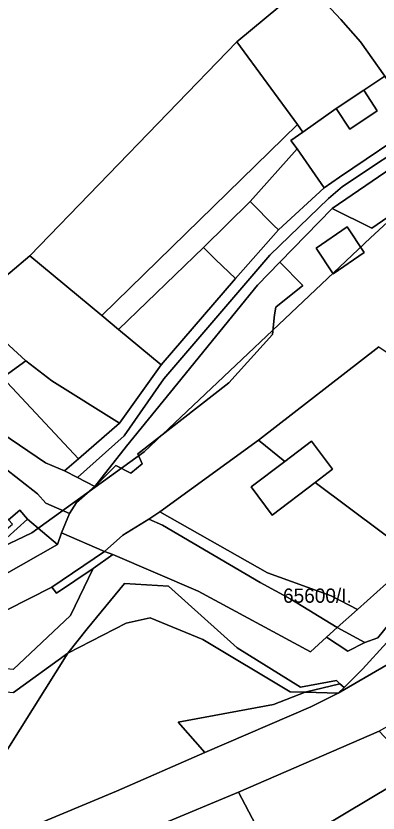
# Model space of a CAD drawing. Extents: x -521261 to -517465, y -1182764 to -1179456.
# Drawn here: x -519071.1 to -518943.8, y -1182060.3 to -1181780.6 of the extents above; entities that cross this region are included whole.
import ezdxf

# ---------------------------------------------------------------- set-up
doc = ezdxf.new("R2010")
doc.units = 0
for name, color, linetype in [('95560013', 7, 'Continuous'), ('95590013', 7, 'Continuous'), ('95610013', 7, 'Continuous'), ('95630013', 7, 'Continuous'), ('95640013', 7, 'Continuous'), ('95660013', 7, 'Continuous')]:
    doc.layers.add(name, color=color, linetype=linetype)

msp = doc.modelspace()

# ---------------------------------------------------------------- linework, layer by layer
at = {"layer": '95560013'}
for points in [[(-519087.04, -1181882.36), (-519066.19, -1181864.73), (-519040.9, -1181885.72), (-519035.04, -1181890.57), (-519020.01, -1181903), (-519034.69, -1181923.51), (-519058.47, -1181908.66), (-519067.58, -1181901.65), (-519076.36, -1181893.5), (-519077.48, -1181892.33), (-519081.67, -1181887.94)], [(-518943.53, -1181896.7), (-518896.41, -1181928.2), (-518898.82, -1181933.95), (-518910.09, -1181942.77), (-518918.49, -1181954.45), (-518930.7, -1181970.59), (-518965.92, -1181944.29), (-518959.85, -1181939.68), (-518967.28, -1181929.78), (-518976.64, -1181936.92), (-518985.81, -1181929.52)], [(-519088.08, -1181916.29), (-519075.82, -1181907.51), (-519049.15, -1181935.98), (-519054.08, -1181940.22), (-519060.67, -1181937.45), (-519082.36, -1181922.81)], [(-518985.81, -1181929.52), (-518976.64, -1181936.92), (-518988.39, -1181945.89), (-518981.04, -1181955.77), (-518965.92, -1181944.29), (-518930.7, -1181970.59), (-518951.03, -1181988.87), (-518960.26, -1181984.07), (-518982.66, -1181976.03), (-519020.51, -1181954.59)], [(-519032.35, -1181993.68), (-519023.89, -1181991.86), (-519005.47, -1181999.42), (-518974.73, -1182017.76), (-518969.43, -1182017.88), (-518980.58, -1182022.19), (-519014.12, -1182028.45), (-519004.74, -1182039.1), (-519035.76, -1182052.6), (-519084.93, -1182073.15), (-519090.2, -1182063.54), (-519052.86, -1182004.21)], [(-519071.99, -1182018.05), (-519052.86, -1182004.21), (-519090.2, -1182063.54), (-519084.93, -1182073.15), (-519102.81, -1182080.62), (-519119.74, -1182088.73), (-519152.16, -1182054.92), (-519144.87, -1182052.15), (-519120.85, -1182036.4), (-519105.37, -1182029.49), (-519087.95, -1182016.65)], [(-518957.82, -1182018.26), (-518967.5, -1182023), (-519004.74, -1182039.1), (-519014.12, -1182028.45), (-518980.58, -1182022.19), (-518969.43, -1182017.88)]]:
    msp.add_lwpolyline(points, close=True, dxfattribs=at)
at = {"layer": '95590013'}
for points in [[(-518986.79, -1181749.85), (-518972.73, -1181724.81), (-518938.29, -1181774.74), (-518915.75, -1181808.56), (-518929.6, -1181818.43), (-518941.47, -1181801.69), (-518950.05, -1181789.67), (-518956.94, -1181781.84), (-518968.7, -1181769.11)], [(-518948.89, -1181806.68), (-518941.47, -1181801.69), (-518929.6, -1181818.43), (-518957.37, -1181837.14), (-518962.74, -1181840.92), (-518972.32, -1181827.26), (-518974.44, -1181824.24), (-518970.25, -1181821.36), (-518958.55, -1181813.11), (-518953.78, -1181820.27), (-518944.13, -1181813.85)]]:
    msp.add_lwpolyline(points, close=True, dxfattribs=at)
at = {"layer": '95610013'}
for points in [[(-519074.15, -1181676.23), (-519053.88, -1181700.18), (-519021, -1181726.81), (-518986.79, -1181749.85), (-518968.7, -1181769.11), (-518993.46, -1181789.66), (-519066.19, -1181864.73), (-519087.04, -1181882.36), (-519108.76, -1181856.75), (-519103.21, -1181844.57), (-519100.47, -1181806.98), (-519098.36, -1181782.29)], [(-518993.46, -1181789.66), (-518972.2, -1181818.68), (-519040.9, -1181885.72), (-519066.19, -1181864.73)], [(-518972.32, -1181827.26), (-518962.74, -1181840.92), (-518978.77, -1181855.67), (-518980.43, -1181854.07), (-518988.38, -1181846.1), (-518988.81, -1181845.66)], [(-519005.13, -1181861.89), (-519004.67, -1181862.34), (-519000.93, -1181866.1), (-518993.99, -1181872.67), (-519020.01, -1181903), (-519035.04, -1181890.57)], [(-519071.05, -1181904.12), (-519067.58, -1181901.65), (-519058.47, -1181908.66), (-519034.69, -1181923.51), (-519049.15, -1181935.98), (-519075.82, -1181907.51), (-519074.07, -1181906.27)], [(-519067.07, -1181957.19), (-519056.53, -1181966.11), (-519094.94, -1181987.78), (-519097.7, -1181985.93), (-519081.64, -1181970.32)], [(-519056.84, -1181983.21), (-519043.95, -1181974.52), (-519051.9, -1181990.97), (-519072.08, -1182009.92), (-519097.34, -1182007.47), (-519109.68, -1182020.3), (-519126.93, -1182028.03), (-519148.1, -1182043.62), (-519159.13, -1182046.65), (-519135.97, -1182021.78), (-519098.32, -1182001.18), (-519058.43, -1181981.09)], [(-518943.48, -1182031.64), (-518930.34, -1182045.53), (-518980.94, -1182075.7), (-518992.91, -1182053.04)], [(-518930.34, -1182045.53), (-518930.08, -1182052.61), (-518938.53, -1182068.6), (-518961.45, -1182094.69), (-518976.16, -1182103.22), (-518974.22, -1182095.54), (-518973.1, -1182091.72), (-518980.94, -1182075.7)]]:
    msp.add_lwpolyline(points, close=True, dxfattribs=at)
at = {"layer": '95630013'}
for points in [[(-518858.89, -1181774.18), (-518856.75, -1181777.08), (-518884.89, -1181790.4), (-518918.2, -1181814.44), (-518928.09, -1181821.69), (-518956.34, -1181840.44), (-518961.29, -1181844.65), (-518981.81, -1181864.59), (-519019.13, -1181907.93), (-519033.11, -1181927.89), (-519049.5, -1181942.57), (-519054.08, -1181940.22), (-519049.15, -1181935.98), (-519034.69, -1181923.51), (-519020.01, -1181903), (-518993.99, -1181872.67), (-518978.77, -1181855.67), (-518962.74, -1181840.92), (-518957.37, -1181837.14), (-518929.6, -1181818.43), (-518915.75, -1181808.56), (-518900.34, -1181797.86), (-518886.24, -1181787.4)], [(-519069.77, -1181954.04), (-519067.07, -1181957.19), (-519081.64, -1181970.32), (-519097.7, -1181985.93), (-519165.3, -1182021.68), (-519165.21, -1182020.25), (-519165.02, -1182017.38), (-519121.4, -1181992.9), (-519097.69, -1181980.06), (-519087.01, -1181971.27), (-519072.29, -1181958.97), (-519073.7, -1181957.38)], [(-518922, -1181977.76), (-518939.98, -1181993.92), (-518943.88, -1181998.78), (-518948.44, -1182000.47), (-518958.19, -1181995.18), (-518951.03, -1181988.87), (-518930.7, -1181970.59)], [(-519017.46, -1181980.74), (-518993.32, -1182002.29), (-518971.14, -1182016.15), (-518958.48, -1182013.83), (-518957.23, -1182014.96), (-518969.43, -1182017.88), (-518974.73, -1182017.76), (-519005.47, -1181999.42), (-519023.89, -1181991.86), (-519032.35, -1181993.68), (-519052.86, -1182004.21), (-519046.11, -1181995.72), (-519032.93, -1181979.72)], [(-518961.97, -1181998.64), (-518958.19, -1181995.18), (-518948.44, -1182000.47), (-518954.51, -1182003.49)], [(-518955.79, -1182016.24), (-518957.82, -1182018.26), (-518969.43, -1182017.88), (-518957.23, -1182014.96)]]:
    msp.add_lwpolyline(points, close=True, dxfattribs=at)
for points in [[(-519072.08, -1182009.92), (-519051.9, -1181990.97), (-519043.95, -1181974.52), (-519037.03, -1181969.53), (-519007.07, -1181982.5), (-518967.52, -1182003.69), (-518961.97, -1181998.64), (-518954.51, -1182003.49), (-518948.44, -1182000.47), (-518943.88, -1181998.78), (-518939.98, -1181993.92)], [(-518940.71, -1182000.44), (-518949.32, -1182009.8), (-518955.79, -1182016.24), (-518957.23, -1182014.96), (-518958.48, -1182013.83), (-518971.14, -1182016.15), (-518993.32, -1182002.29), (-519017.46, -1181980.74), (-519032.93, -1181979.72), (-519046.11, -1181995.72), (-519052.86, -1182004.21), (-519071.99, -1182018.05)]]:
    msp.add_lwpolyline(points, dxfattribs=at)
at = {"layer": '95640013'}
for points in [[(-518968.7, -1181769.11), (-518956.94, -1181781.84), (-518950.05, -1181789.67), (-518941.47, -1181801.69), (-518948.89, -1181806.68), (-518958.55, -1181813.11), (-518970.25, -1181821.36), (-518972.2, -1181818.68), (-518993.46, -1181789.66)], [(-518958.55, -1181813.11), (-518948.89, -1181806.68), (-518944.13, -1181813.85), (-518953.78, -1181820.27)], [(-518915.57, -1181817.81), (-518959.96, -1181848.19), (-518978.35, -1181867.02), (-518986.16, -1181875.1), (-519014.2, -1181909.44), (-519032.21, -1181931.59), (-519043.36, -1181945.69), (-519049.5, -1181942.57), (-519033.11, -1181927.89), (-519019.13, -1181907.93), (-518981.81, -1181864.59), (-518961.29, -1181844.65), (-518956.34, -1181840.44), (-518928.09, -1181821.69), (-518918.2, -1181814.44)], [(-518970.25, -1181821.36), (-518974.44, -1181824.24), (-518972.32, -1181827.26), (-518988.81, -1181845.66), (-519005.13, -1181861.89), (-519035.04, -1181890.57), (-519040.9, -1181885.72), (-518972.2, -1181818.68)], [(-518915.57, -1181817.81), (-518903.79, -1181832.41), (-518912.66, -1181832.1), (-518945.99, -1181855.1), (-518959.96, -1181848.19)], [(-518988.81, -1181845.66), (-518988.38, -1181846.1), (-518980.43, -1181854.07), (-518978.77, -1181855.67), (-518993.99, -1181872.67), (-519000.93, -1181866.1), (-519004.67, -1181862.34), (-519005.13, -1181861.89)], [(-518954.65, -1181854.62), (-518948.77, -1181863.58), (-518959.67, -1181871.06), (-518965.61, -1181862.09)], [(-518954.65, -1181854.62), (-518965.61, -1181862.09), (-518959.67, -1181871.06), (-518948.77, -1181863.58)], [(-518986.16, -1181875.1), (-518978.35, -1181867.02), (-518970.27, -1181875.14), (-518979.79, -1181882.79), (-518980.21, -1181885.53), (-518980.91, -1181892.34), (-518996.32, -1181909.32), (-519028.28, -1181934.28), (-519026.78, -1181937.75), (-519030.71, -1181941.03), (-519035.97, -1181938.38), (-519043.36, -1181945.69), (-519032.21, -1181931.59), (-519014.2, -1181909.44)], [(-519077.48, -1181892.33), (-519076.36, -1181893.5), (-519067.58, -1181901.65), (-519071.05, -1181904.12), (-519074.07, -1181906.27), (-519075.82, -1181907.51), (-519088.08, -1181916.29), (-519094.93, -1181908.48), (-519095.7, -1181907.61), (-519099.95, -1181901.33), (-519100.73, -1181900.15), (-519096.49, -1181896.99), (-519091.49, -1181893.26), (-519089.25, -1181896.53), (-519088.35, -1181895.88), (-519086.92, -1181897.86), (-519082.92, -1181896.68), (-519080.21, -1181894.34)], [(-519113.34, -1181907.98), (-519111.2, -1181906.26), (-519101.35, -1181915.82), (-519087.5, -1181929.61), (-519063.46, -1181948.28), (-519060.64, -1181951.52), (-519052.26, -1181955.25), (-519055.06, -1181962.04), (-519056.53, -1181966.11), (-519067.07, -1181957.19), (-519069.77, -1181954.04), (-519073.7, -1181957.38), (-519078.64, -1181952.15), (-519098.12, -1181927.63), (-519104.14, -1181920.4), (-519107.21, -1181916.38)], [(-518976.64, -1181936.92), (-518967.28, -1181929.78), (-518959.85, -1181939.68), (-518965.92, -1181944.29), (-518981.04, -1181955.77), (-518988.39, -1181945.89)], [(-519020.51, -1181954.59), (-518982.66, -1181976.03), (-518960.26, -1181984.07), (-518951.03, -1181988.87), (-518958.19, -1181995.18), (-518974.49, -1181985.3), (-518985.27, -1181979.47), (-519019.53, -1181959.33), (-519024.41, -1181957.14)], [(-519019.53, -1181959.33), (-518985.27, -1181979.47), (-518974.49, -1181985.3), (-518958.19, -1181995.18), (-518961.97, -1181998.64), (-518967.52, -1182003.69), (-519007.07, -1181982.5), (-519037.03, -1181969.53), (-519040, -1181968.57), (-519033.57, -1181962.86), (-519024.41, -1181957.14)], [(-519055.06, -1181962.04), (-519040, -1181968.57), (-519058.43, -1181981.09), (-519098.32, -1182001.18), (-519135.97, -1182021.78), (-519164.56, -1182037.39), (-519199.92, -1182056.85), (-519222.3, -1182068.89), (-519231.14, -1182073.63), (-519228.29, -1182058.88), (-519219.06, -1182053.68), (-519196.2, -1182041.94), (-519165.22, -1182025.6), (-519165.3, -1182021.68), (-519097.7, -1181985.93), (-519094.94, -1181987.78), (-519056.53, -1181966.11)], [(-519037.03, -1181969.53), (-519043.95, -1181974.52), (-519056.84, -1181983.21), (-519058.43, -1181981.09), (-519040, -1181968.57)], [(-518940.71, -1182000.44), (-518933.59, -1182001.92), (-518938.91, -1182007.31), (-518957.82, -1182018.26), (-518955.79, -1182016.24), (-518949.32, -1182009.8)], [(-519020.41, -1182064.46), (-518992.91, -1182053.04), (-518980.94, -1182075.7), (-518973.1, -1182091.72), (-518974.22, -1182095.54), (-518976.16, -1182103.22), (-519006.27, -1182117.14), (-519010.79, -1182110.87), (-519031.78, -1182080.78)]]:
    msp.add_lwpolyline(points, close=True, dxfattribs=at)
for points in [[(-518943.53, -1181896.7), (-518985.81, -1181929.52), (-519020.51, -1181954.59), (-519024.41, -1181957.14), (-519033.57, -1181962.86), (-519040, -1181968.57), (-519055.06, -1181962.04), (-519052.26, -1181955.25), (-519049.85, -1181951.39), (-519043.36, -1181945.69), (-519035.97, -1181938.38), (-519030.71, -1181941.03), (-519026.78, -1181937.75), (-519028.28, -1181934.28), (-518996.32, -1181909.32), (-518980.91, -1181892.34), (-518980.21, -1181885.53), (-518979.79, -1181882.79), (-518970.27, -1181875.14), (-518978.35, -1181867.02), (-518959.96, -1181848.19), (-518945.99, -1181855.1), (-518912.66, -1181832.1)], [(-519084.93, -1182073.15), (-519035.76, -1182052.6), (-519004.74, -1182039.1), (-518967.5, -1182023), (-518957.82, -1182018.26), (-518938.91, -1182007.31), (-518928.98, -1182002.39), (-518906.12, -1181990.72), (-518904.36, -1181989.62), (-518888.19, -1181976.5), (-518853.28, -1181947.39), (-518848.27, -1181943.05), (-518812.53, -1181910.12), (-518791.39, -1181896.52), (-518780.73, -1181891.86), (-518762.52, -1181884.14)], [(-518740.3, -1181896.33), (-518841.96, -1181963.21), (-518854.3, -1181971.43), (-518872.89, -1181988.08), (-518883.86, -1181997.98), (-518917.64, -1182016.73), (-518932.82, -1182025.58), (-518943.48, -1182031.64), (-518992.91, -1182053.04), (-519020.41, -1182064.46)], [(-519082.36, -1181922.81), (-519060.67, -1181937.45), (-519054.08, -1181940.22), (-519049.5, -1181942.57), (-519043.36, -1181945.69), (-519049.85, -1181951.39), (-519052.26, -1181955.25), (-519060.64, -1181951.52), (-519063.46, -1181948.28), (-519087.5, -1181929.61)]]:
    msp.add_lwpolyline(points, dxfattribs=at)
at = {"layer": '95660013'}
for points in [[(-518591, -1181563), (-518568, -1181628), (-518541, -1181680), (-518535.5, -1181702.5), (-518541, -1181732.5), (-518554.5, -1181761), (-518572, -1181787), (-518650.5, -1181761), (-518758, -1181742.5), (-518786, -1181742.5), (-518805, -1181750), (-518831, -1181763.5), (-518903, -1181818.5), (-518946.5, -1181858.5), (-519026, -1181933.5), (-519065.5, -1181962), (-519076, -1181967)], [(-519076, -1181967), (-519065.5, -1181962), (-519026, -1181933.5), (-518946.5, -1181858.5), (-518903, -1181818.5), (-518831, -1181763.5), (-518805, -1181750), (-518786, -1181742.5), (-518758, -1181742.5)]]:
    msp.add_lwpolyline(points, dxfattribs=at)

# ---------------------------------------------------------------- texts
msp.add_text('65600/I.', height=5, rotation=0, dxfattribs=at).set_placement((-518977.23, -1181986.53))

doc.saveas('drawing.dxf')
